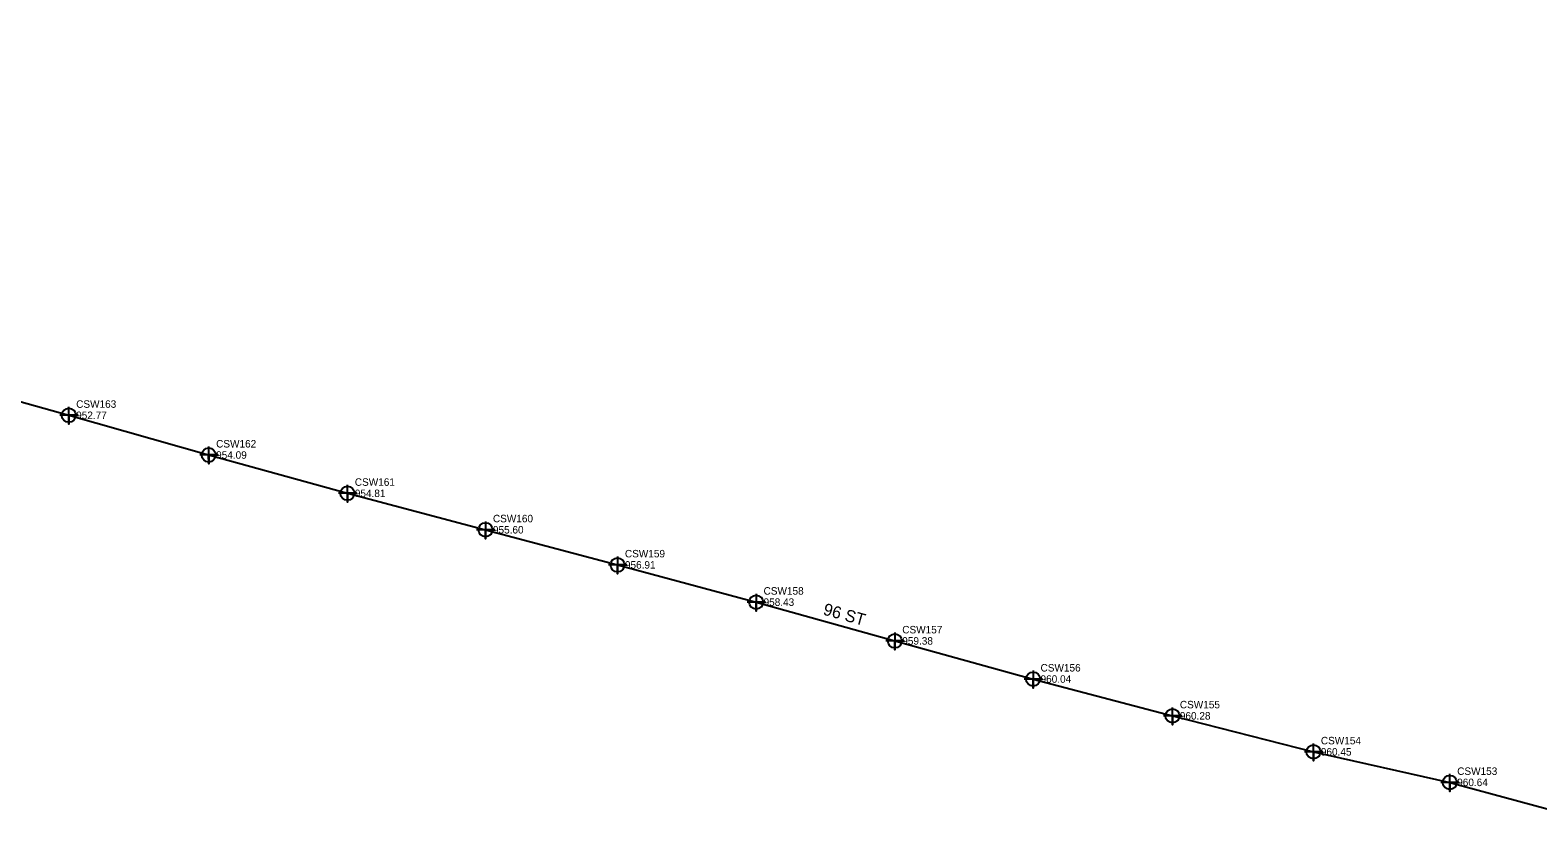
# Model space of a CAD drawing. Extents: x 1182504 to 1186036, y 573002 to 575111.
# Drawn here: x 1182988 to 1183491, y 574205 to 574469 of the extents above; entities that cross this region are included whole.
import ezdxf

# ---------------------------------------------------------------- set-up
doc = ezdxf.new("R2010")
doc.units = 0
for name, color, linetype in [('Exist Utilities Telephone UG Conduit SUE LOS B', 7, 'Continuous'), ('Exist Utilities Telephone UG Conduit SUE LOS B Cogo Elevation', 7, 'Continuous'), ('Exist Utilities Telephone UG Conduit SUE LOS B Cogo Number', 7, 'Continuous'), ('Exist Utilities Telephone UG Conduit SUE LOS B Cogo Point CELL', 7, 'Continuous'), ('Exist Utilities Telephone UG Conduit SUE LOS B Text', 7, 'Continuous')]:
    doc.layers.add(name, color=color, linetype=linetype)

msp = doc.modelspace()

# ---------------------------------------------------------------- linework, layer by layer
at = {"layer": 'Exist Utilities Telephone UG Conduit SUE LOS B'}
msp.add_lwpolyline([(1182508.5, 574468.79), (1182551.34, 574456.98), (1182596.76, 574444.59), (1182640.9, 574433.89), (1182683.93, 574421.8), (1182729.54, 574414.63), (1182775.26, 574402.85), (1182821.5, 574389.91), (1182867.02, 574377.15), (1182909.89, 574365.68), (1182955.8, 574352.93), (1183001.1, 574340.19), (1183047.8, 574326.93), (1183094.08, 574314.14), (1183140.16, 574301.96), (1183184.2, 574290.24), (1183230.46, 574277.8), (1183276.74, 574264.86), (1183322.88, 574252.13), (1183369.36, 574239.84), (1183416.41, 574227.82), (1183461.9, 574217.61), (1183507.97, 574205.1)], dxfattribs=at)
at = {"layer": 'Exist Utilities Telephone UG Conduit SUE LOS B Cogo Point CELL'}
for points in [[(1183001.08, 574343.01), (1183001.12, 574337.19), (1183001.1, 574340.19), (1183004.12, 574340.19), (1182998.12, 574340.19)], [(1183047.79, 574329.75), (1183047.82, 574323.93), (1183047.8, 574326.93), (1183050.82, 574326.93), (1183044.82, 574326.93)], [(1183094.07, 574316.96), (1183094.1, 574311.14), (1183094.08, 574314.14), (1183097.1, 574314.14), (1183091.1, 574314.14)], [(1183140.15, 574304.77), (1183140.18, 574298.96), (1183140.16, 574301.96), (1183143.18, 574301.96), (1183137.18, 574301.96)], [(1183184.19, 574293.06), (1183184.22, 574287.24), (1183184.2, 574290.24), (1183187.22, 574290.24), (1183181.22, 574290.24)], [(1183230.45, 574280.62), (1183230.48, 574274.8), (1183230.46, 574277.8), (1183233.48, 574277.8), (1183227.48, 574277.8)], [(1183276.72, 574267.67), (1183276.76, 574261.86), (1183276.74, 574264.86), (1183279.76, 574264.86), (1183273.76, 574264.86)], [(1183322.87, 574254.95), (1183322.9, 574249.13), (1183322.88, 574252.13), (1183325.9, 574252.13), (1183319.9, 574252.13)], [(1183369.34, 574242.65), (1183369.38, 574236.84), (1183369.36, 574239.84), (1183372.38, 574239.84), (1183366.38, 574239.84)], [(1183416.39, 574230.63), (1183416.42, 574224.82), (1183416.41, 574227.82), (1183419.42, 574227.82), (1183413.42, 574227.82)], [(1183461.88, 574220.42), (1183461.92, 574214.61), (1183461.9, 574217.61), (1183464.92, 574217.61), (1183458.92, 574217.61)]]:
    msp.add_lwpolyline(points, dxfattribs=at)
for centre in [(1183001.12, 574340.19), (1183047.82, 574326.93), (1183094.1, 574314.14), (1183140.18, 574301.96), (1183184.22, 574290.24), (1183230.48, 574277.8), (1183276.76, 574264.86), (1183322.9, 574252.13), (1183369.38, 574239.84), (1183416.42, 574227.82), (1183461.92, 574217.61)]:
    msp.add_circle(centre, 2.34, dxfattribs=at)

# ---------------------------------------------------------------- texts
at = {"layer": 'Exist Utilities Telephone UG Conduit SUE LOS B Cogo Elevation'}
for s, p in [('952.77', (1183003.6, 574338.94)), ('954.09', (1183050.3, 574325.68)), ('954.81', (1183096.58, 574312.89)), ('955.60', (1183142.66, 574300.71)), ('956.91', (1183186.7, 574288.99)), ('958.43', (1183232.96, 574276.55)), ('959.38', (1183279.24, 574263.61)), ('960.04', (1183325.38, 574250.88)), ('960.28', (1183371.86, 574238.59)), ('960.45', (1183418.91, 574226.57)), ('960.64', (1183464.4, 574216.36))]:
    msp.add_text(s, height=2.5, dxfattribs=at).set_placement(p)
at = {"layer": 'Exist Utilities Telephone UG Conduit SUE LOS B Cogo Number'}
for s, p in [('CSW163', (1183003.6, 574342.69)), ('CSW162', (1183050.3, 574329.43)), ('CSW161', (1183096.58, 574316.64)), ('CSW160', (1183142.66, 574304.46)), ('CSW159', (1183186.7, 574292.74)), ('CSW158', (1183232.96, 574280.3)), ('CSW157', (1183279.24, 574267.36)), ('CSW156', (1183325.38, 574254.63)), ('CSW155', (1183371.86, 574242.34)), ('CSW154', (1183418.91, 574230.32)), ('CSW153', (1183464.4, 574220.11))]:
    msp.add_text(s, height=2.5, dxfattribs=at).set_placement(p)
at = {"layer": 'Exist Utilities Telephone UG Conduit SUE LOS B Text'}
msp.add_text('96 ST', height=4, rotation=344.3743, dxfattribs=at).set_placement((1183252.57, 574273.69))

doc.saveas('drawing.dxf')
